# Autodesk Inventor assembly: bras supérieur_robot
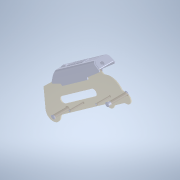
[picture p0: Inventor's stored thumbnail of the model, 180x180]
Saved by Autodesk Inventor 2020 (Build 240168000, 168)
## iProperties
Created: 2018-10
Part Number: bras supérieur_robot
Document SubType Name: Assembly
Designer: bruno
Author: bruno
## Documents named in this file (13)
- C:\Users\bruno\Documents\Systèmes\Mallette Bras robotisé (273265)\Dossier ressources\Maquette Dobot SW2016\bras supérieur_robot.iam
- C:\Users\bruno\Documents\Systèmes\Mallette Bras robotisé (273265)\Dossier ressources\Maquette Dobot SW2016\______43_A.ipt
- C:\Users\bruno\Documents\Systèmes\Mallette Bras robotisé (273265)\Dossier ressources\Maquette Dobot SW2016\_______1_A.ipt
- C:\Users\bruno\Documents\Systèmes\Mallette Bras robotisé (273265)\Dossier ressources\Maquette Dobot SW2016\_________4_A.ipt
- C:\Users\bruno\Documents\Systèmes\Mallette Bras robotisé (273265)\Dossier ressources\Maquette Dobot SW2016\______42_A.ipt
- C:\Users\bruno\Documents\Systèmes\Mallette Bras robotisé (273265)\Dossier ressources\Maquette Dobot SW2016\_____41_A.ipt
- C:\Users\bruno\Documents\Systèmes\Mallette Bras robotisé (273265)\Dossier ressources\Maquette Dobot SW2016\_____40_A.ipt
- C:\Users\bruno\Documents\Systèmes\Mallette Bras robotisé (273265)\Dossier ressources\Maquette Dobot SW2016\_____38_A.ipt
- C:\Users\bruno\Documents\Systèmes\Mallette Bras robotisé (273265)\Dossier ressources\Maquette Dobot SW2016\_____M2_5_A.ipt
- C:\Users\bruno\Documents\Systèmes\Mallette Bras robotisé (273265)\Dossier ressources\Maquette Dobot SW2016\MEER0005_A.ipt
- C:\Users\bruno\Documents\Systèmes\Mallette Bras robotisé (273265)\Dossier ressources\Maquette Dobot SW2016\_______36_A.ipt
- C:\Users\bruno\Documents\Systèmes\Mallette Bras robotisé (273265)\Dossier ressources\Maquette Dobot SW2016\__34_A.ipt
- C:\Users\bruno\Documents\Systèmes\Mallette Bras robotisé (273265)\Dossier ressources\Maquette Dobot SW2016\_______22_A.ipt
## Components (22 placed, 12 different names)
1. ______43_A:1
2. _______1_A:1
3. _________4_A:1
4. _________4_A:2
5. _________4_A:3
6. _________4_A:4
7. ______42_A:1
8. _____41_A:1
9. _____40_A:1
10. _____38_A:1
11. _____M2_5_A:1
12. _____M2_5_A:2
13. _____M2_5_A:3
14. _____M2_5_A:4
15. _____38_A:2
16. MEER0005_A:1
17. MEER0005_A:2
18. _______36_A:1
19. __34_A:1
20. MEER0005_A:3
21. MEER0005_A:4
22. _______22_A:1
